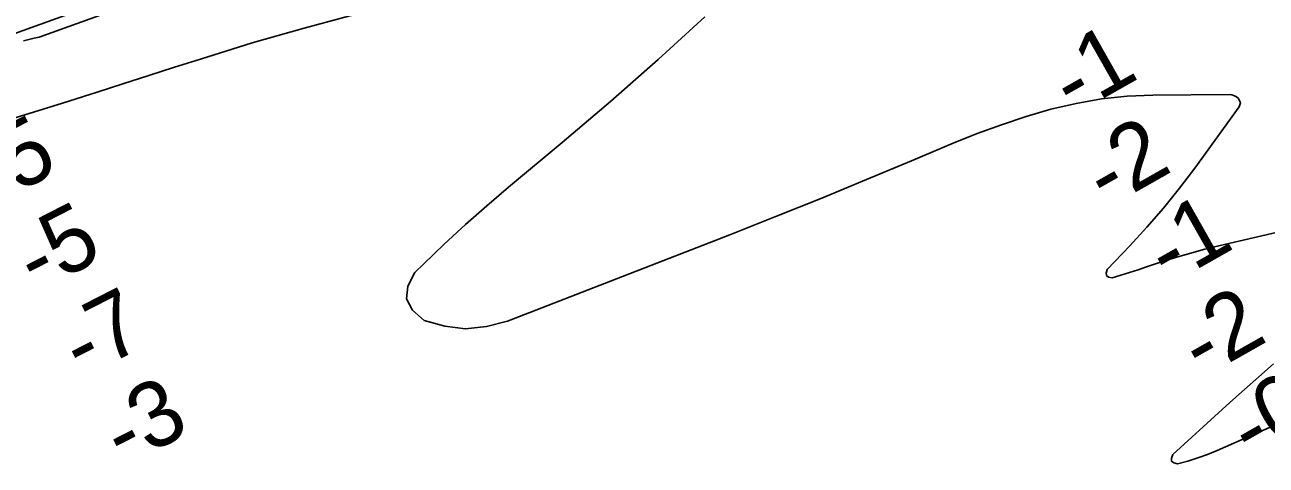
# Model space of a CAD drawing. Extents: x 3177385 to 3215275, y 903885 to 929304.
# Drawn here: x 3189350 to 3190624, y 912601 to 913053 of the extents above; entities that cross this region are included whole.
import ezdxf

# ---------------------------------------------------------------- set-up
doc = ezdxf.new("R2010")
doc.units = 0
for name, color, linetype in [('V-RIVR-RANG', 7, 'Continuous'), ('V-TOPO-DPTH', 7, 'Continuous'), ('V-TOPO-GNAM-IDEN', 7, 'Continuous'), ('V-TOPO-MINR', 7, 'Continuous')]:
    doc.layers.add(name, color=color, linetype=linetype)

msp = doc.modelspace()

# ---------------------------------------------------------------- linework, layer by layer
at = {"layer": 'V-TOPO-DPTH'}
for points in [[(3191498.2, 913338.5), (3190263, 913364.6), (3190258.5, 913363.6), (3190255.7, 913362.7), (3190254.2, 913362.1), (3190250, 913360.3), (3190246.5, 913358.8), (3190243, 913357.3), (3190239.5, 913355.8), (3190236, 913354.3), (3189364.5, 913040.7), (3189359.1, 913039.5), (3189353.7, 913038.2), (3189348.3, 913036.8)], [(3189348.3, 913036.8), (3189353.7, 913038.2), (3189359.1, 913039.5), (3189364.5, 913040.7), (3190236, 913354.3), (3190239.5, 913355.8), (3190243, 913357.3), (3190246.5, 913358.8), (3190250, 913360.3), (3190254.2, 913362.1), (3190255.7, 913362.7), (3190258.5, 913363.6), (3190263, 913364.6), (3191498.2, 913338.5)]]:
    msp.add_lwpolyline(points, dxfattribs=at)
at = {"layer": 'V-TOPO-MINR'}
for points in [[(3191301.8, 913764.6), (3190387.5, 913432.6), (3190374.8, 913429.4), (3190362.3, 913425.7), (3190350, 913421.2), (3190337.9, 913416.3), (3190298.5, 913399.1), (3190266.8, 913385.3), (3190235, 913371.5), (3190203.3, 913357.8), (3190171.5, 913344.2), (3189308.7, 913033.4), (3189300.5, 913029.6), (3189292.3, 913025.8), (3189284.1, 913022), (3189275.9, 913018.2), (3188081.6, 912617.6), (3188053.5, 912603.1), (3188025.4, 912588.7), (3187033.1, 912268.1)], [(3191498.2, 913338.5), (3190263, 913364.6), (3190258.5, 913363.6), (3190255.7, 913362.7), (3190254.2, 913362.1), (3190250, 913360.3), (3190246.5, 913358.8), (3190243, 913357.3), (3190239.5, 913355.8), (3190236, 913354.3), (3189364.5, 913040.7), (3189359.1, 913039.5), (3189353.7, 913038.2), (3189348.3, 913036.8)], [(3189708.4, 913069.4), (3189636.4, 913049.9), (3189609.6, 913042.4), (3189582.9, 913034.7), (3189529.8, 913018.2), (3189503.4, 913009.7), (3189476.9, 913001.2), (3189450.4, 912992.8), (3189423.9, 912984.3), (3189388.2, 912973), (3189358.5, 912963.7), (3189328.6, 912954.6)], [(3190797.6, 912878.2), (3190576.3, 912826.7), (3190560.6, 912822.9), (3190545, 912818.7), (3190529.5, 912814.1), (3190514.1, 912809.2), (3190501, 912804.8), (3190492.2, 912801.9), (3190483.3, 912799.1), (3190474.4, 912796.4), (3190465.5, 912793.7), (3190462, 912794.4), (3190459.8, 912795.9), (3190459.5, 912798.5), (3190460.5, 912802), (3190483.7, 912826.3), (3190501.3, 912845.5), (3190518.4, 912865.2), (3190534.6, 912885.5), (3190550.4, 912906.3), (3190595.9, 912969), (3190597.2, 912973.4), (3190595.3, 912977.6), (3190593.3, 912979.3), (3190591, 912980.6), (3190588.5, 912981.4), (3190585.8, 912981.7), (3190507.5, 912981.2), (3190481, 912980), (3190454.7, 912977.4), (3190428.7, 912972.7), (3190402.8, 912966.7), (3190377.3, 912959.1), (3190352.1, 912950.8), (3190327.1, 912941.6), (3190302.4, 912931.7), (3190259.7, 912913.6), (3190213.6, 912894.4), (3190167.5, 912875.4), (3190121.2, 912856.9), (3190074.8, 912838.6), (3189844.9, 912749.3), (3189823.5, 912743.7), (3189802.1, 912741.4), (3189780.8, 912744), (3189759.5, 912749.9), (3189747.7, 912760.4), (3189741.3, 912771.9), (3189742.9, 912785), (3189749.8, 912799.2), (3189759, 912808.1), (3189780.2, 912828.3), (3189801.8, 912848.3), (3189823.8, 912867.6), (3189846.2, 912886.7), (3189901, 912932.5), (3189950.6, 912974.7), (3189999.5, 913017.6), (3190047.6, 913061.5)], [(3190630, 912641.4), (3190573.5, 912616.5), (3190563.6, 912612.4), (3190553.5, 912608.7), (3190543.2, 912605.5), (3190532.8, 912602.7), (3190529, 912603.7), (3190526.6, 912605.5), (3190526.5, 912608.5), (3190527.8, 912612.2), (3190586.5, 912665.6), (3190601.3, 912679), (3190616.2, 912692.1), (3190631.3, 912705.2)]]:
    msp.add_lwpolyline(points, dxfattribs=at)

# ---------------------------------------------------------------- texts
at = {"layer": 'V-RIVR-RANG'}
for s, rotation, p in [('-1', 29.5319, (3190425.5, 912960)), ('-5', 27.0992, (3189315.7, 912867.6)), ('-2', 29.5319, (3190460, 912864.6)), ('-5', 27.0992, (3189361.1, 912778.4)), ('-1', 29.5319, (3190523.4, 912785.6)), ('-7', 27.0992, (3189407.8, 912690)), ('-2', 29.5319, (3190557.8, 912690.2)), ('-3', 27.0992, (3189450.3, 912599.4)), ('-0', 29.5319, (3190608.4, 912603.9))]:
    msp.add_text(s, height=67, rotation=rotation, dxfattribs=at).set_placement(p)
at = {"layer": 'V-TOPO-GNAM-IDEN'}
msp.add_text('TARBERT LANDING DISCHARGE RANGE', height=100, rotation=298.2461, dxfattribs=at).set_placement((3189069.7, 912709.7))

doc.saveas('drawing.dxf')
